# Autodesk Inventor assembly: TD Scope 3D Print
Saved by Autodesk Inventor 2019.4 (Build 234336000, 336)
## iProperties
Created: 2020-09
Part Number: TD Scope 3D Print
Document SubType Name: Assembly
Designer: Administrator
Title: TD Scope 3D Print v28
Author: Administrator
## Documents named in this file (9)
- c:\worker\convert-fusion-r07\tmp\job-1\148\output\files\7ea7cde0-15a9-464f-a7a7-e932f6dacad3\6e357bd3-70b6-4be0-8288-8fe059735b8f.iam
- c:\worker\convert-fusion-r07\tmp\job-1\148\output\files\7ea7cde0-15a9-464f-a7a7-e932f6dacad3\Tube.ipt
- c:\worker\convert-fusion-r07\tmp\job-1\148\output\files\7ea7cde0-15a9-464f-a7a7-e932f6dacad3\Lens.ipt
- c:\worker\convert-fusion-r07\tmp\job-1\148\output\files\7ea7cde0-15a9-464f-a7a7-e932f6dacad3\Front Lens Holder.ipt
- c:\worker\convert-fusion-r07\tmp\job-1\148\output\files\7ea7cde0-15a9-464f-a7a7-e932f6dacad3\Front Lens Spacer.ipt
- c:\worker\convert-fusion-r07\tmp\job-1\148\output\files\7ea7cde0-15a9-464f-a7a7-e932f6dacad3\Rear Mount.ipt
- c:\worker\convert-fusion-r07\tmp\job-1\148\output\files\7ea7cde0-15a9-464f-a7a7-e932f6dacad3\Eyepiece Holder.ipt
- c:\worker\convert-fusion-r07\tmp\job-1\148\output\files\7ea7cde0-15a9-464f-a7a7-e932f6dacad3\Focuser Retention.ipt
- c:\worker\convert-fusion-r07\tmp\job-1\148\output\files\7ea7cde0-15a9-464f-a7a7-e932f6dacad3\Light Stop.ipt
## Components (8 placed, 8 different names)
1. Tube:1
2. Lens:1
3. Front Lens Holder:1
4. Front Lens Spacer:1
5. Rear Mount:1
6. Eyepiece Holder:1
7. Focuser Retention:1
8. Light Stop:1
